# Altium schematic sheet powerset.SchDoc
size A3
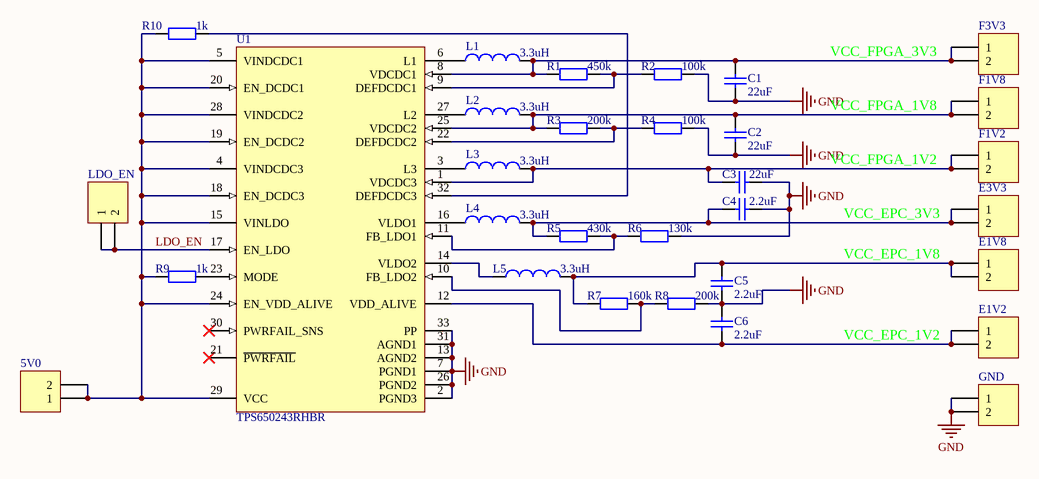
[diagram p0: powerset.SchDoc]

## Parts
5V0  Header 2  [HDR1X2]  (value not drawn)
C1  value 22uF  [1608[0603]]  (hidden comment: Cap Semi)
C2  value 22uF  [1608[0603]]  (hidden comment: Cap Semi)
C3  value 22uF  [1608[0603]]  (hidden comment: Cap Semi)
C4  value 2.2uF  [1608[0603]]  (hidden comment: Cap Semi)
C5  value 2.2uF  [1608[0603]]  (hidden comment: Cap Semi)
C6  value 2.2uF  [1608[0603]]  (hidden comment: Cap Semi)
E1V2  Header 2  [HDR1X2]  (value not drawn)
E1V8  Header 2  [HDR1X2]  (value not drawn)
E3V3  Header 2  [HDR1X2]  (value not drawn)
F1V2  Header 2  [HDR1X2]  (value not drawn)
F1V8  Header 2  [HDR1X2]  (value not drawn)
F3V3  Header 2  [HDR1X2]  (value not drawn)
GND  Header 2  [HDR1X2]  (value not drawn)
L1  value 3.3uH  [2029]  (hidden comment: Inductor)
L2  value 3.3uH  [2029]  (hidden comment: Inductor)
L3  value 3.3uH  [2029]  (hidden comment: Inductor)
L4  value 3.3uH  [2029]  (hidden comment: Inductor)
L5  value 3.3uH  [2029]  (hidden comment: Inductor)
LDO_EN  Header 2  [HDR1X2]  (value not drawn)
R1  value 450k  [0603C]  (hidden comment: NC)
R2  value 100k  [0603C]  (hidden comment: NC)
R3  value 200k  [0603C]  (hidden comment: NC)
R4  value 100k  [0603C]  (hidden comment: NC)
R5  value 430k  [0603C]  (hidden comment: NC)
R6  value 130k  [0603C]  (hidden comment: NC)
R7  value 160k  [0603R]  (hidden comment: NC)
R8  value 200k  [0603R]  (hidden comment: NC)
R9  value 1k  [0603R]  (hidden comment: NC)
R10  value 1k  [0603R]  (hidden comment: NC)
U1  TPS650243RHBR  [TPS650243RHBT]

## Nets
GND: C1.2 C2.2 C3.2 C4.2 C5.2 C6.1 GND.1 GND.2 R2.2 R4.2 R6.2 R8.2 U1.2(PGND3) U1.7(PGND1) U1.13(AGND2) U1.26(PGND2) U1.31(AGND1) U1.33(PP)
LDO_EN: LDO_EN.1 LDO_EN.2 U1.17(EN_LDO)
Net5V0_1: 5V0.1 5V0.2 R9.2 R10.2 U1.4(VINDCDC3) U1.5(VINDCDC1) U1.15(VINLDO) U1.18(EN_DCDC3) U1.19(EN_DCDC2) U1.20(EN_DCDC1) U1.24(EN_VDD_ALIVE) U1.28(VINDCDC2) U1.29(VCC)
NetC1_1: C1.1 F3V3.1 F3V3.2 L1.2 R1.2 U1.8(VDCDC1)
NetC2_1: C2.1 F1V8.1 F1V8.2 L2.2 R3.2 U1.25(VDCDC2)
NetC3_1: C3.1 F1V2.1 F1V2.2 L3.2 U1.1(VDCDC3)
NetC4_1: C4.1 E3V3.1 E3V3.2 L4.2 R5.2
NetC5_1: C5.1 E1V8.1 E1V8.2 L5.2 R7.2
NetC6_2: C6.2 E1V2.1 E1V2.2 U1.12(VDD_ALIVE)
NetL1_1: L1.1 U1.6(L1)
NetL2_1: L2.1 U1.27(L2)
NetL3_1: L3.1 U1.3(L3)
NetL4_1: L4.1 U1.16(VLDO1)
NetL5_1: L5.1 U1.14(VLDO2)
NetR1_1: R1.1 R2.1 U1.9(DEFDCDC1)
NetR3_1: R3.1 R4.1 U1.22(DEFDCDC2)
NetR5_1: R5.1 R6.1 U1.11(FB_LDO1)
NetR7_1: R7.1 R8.1 U1.10(FB_LDO2)
NetR9_1: R9.1 U1.23(MODE)
NetR10_1: R10.1 U1.32(DEFDCDC3)

Not connected (* = marked no-connect by the designer): U1 21(~{PWRFAIL})* 30(PWRFAIL_SNS)*

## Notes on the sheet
- VCC_FPGA_3V3
- VCC_FPGA_1V8
- VCC_FPGA_1V2
- VCC_EPC_3V3
- VCC_EPC_1V8
- VCC_EPC_1V2

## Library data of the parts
5V0 E1V2 E1V8 E3V3 F1V2 F1V8 F3V3 GND LDO_EN = Header 2: Header, 2-Pin
C1-C6 = Cap Semi: Capacitor (Semiconductor SIM Model)
L1-L5 = Inductor: Code_IEC: 1005
R1-R10 = Res2: Resistor
U1 = TPS650243RHBR: Multi-Channel Power Management IC with 2.5 to 6 V Input, -40 to 85 degC, 32-Pin QFN (RHB), Green (RoHS & no Sb/Br); Manufacturer: Texas Instruments; Dynamic Voltage Scaling: TRUE; Rating: Catalog; Regulated Outputs(#): 6; SubFamily: Step-Down Regulator; Vin(Min)(V): 2.5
